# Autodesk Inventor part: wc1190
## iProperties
Shininess: 64.0
Length Units: 11272
Angle Units: 11279
Time Units: 11290
Mass Units: 11286
Length Display Precision: 3
Angle Display Precision: 2
Compacted: True
Part Number: wc1190
Document SubType Name: Modeling
Created: 2004-08
Designer: John Blackburn
Manufacturer: Standard
Standards Organization: Custom
Material: Phenolic
Density: 0.0
Volumn: 0.0
Area: 0.0
PropertySet Name: Model Information
Control State: 0
Master: False
Checked Out: False
Author: John Blackburn
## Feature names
1. Base1
